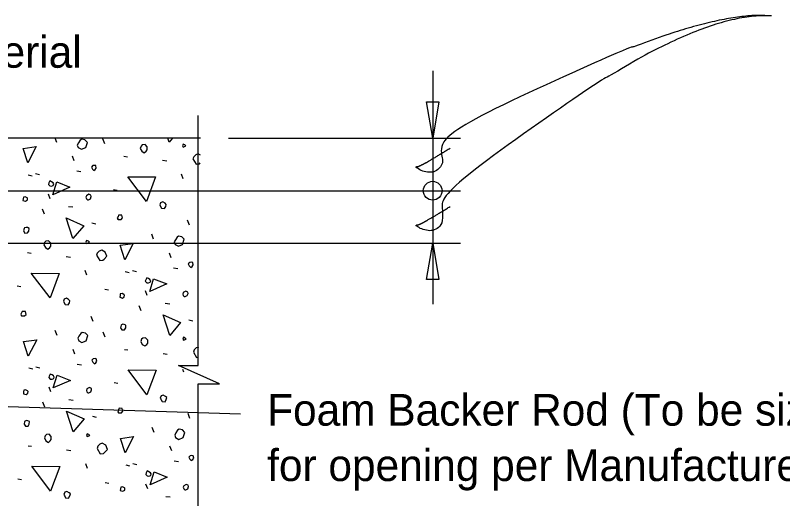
# Model space of a CAD drawing. Extents: x 0 to 15.4, y 0 to 9.7.
# Drawn here: x 5 to 6.829, y 3.173 to 4.325 of the extents above; entities that cross this region are included whole.
import ezdxf

# ---------------------------------------------------------------- set-up
doc = ezdxf.new("R2010")
doc.units = 0
for name, color, linetype in [('Dimension', 7, 'Continuous'), ('Miscellaneous', 7, 'Continuous'), ('SupstrConc', 7, 'Continuous'), ('TextStructures', 7, 'Continuous')]:
    doc.layers.add(name, color=color, linetype=linetype)

msp = doc.modelspace()

# ---------------------------------------------------------------- linework, layer by layer
at = {"layer": 'Dimension'}
for p, q in [((5.9943, 4.1934), (5.9943, 3.7182)), ((5.9943, 4.1934), (5.9943, 3.6362)), ((5.5074, 4.0322), (6.0609, 4.0322)), ((4.0652, 3.9072), (6.0609, 3.9072)), ((3.8815, 3.7822), (6.0609, 3.7822)), ((5.5362, 3.3743), (3.9985, 3.4235))]:
    msp.add_line(p, q, dxfattribs=at)
for points in [[(5.9943, 4.0322), (5.9796, 4.1188), (6.009, 4.1188)], [(5.9943, 3.7822), (6.009, 3.6956), (5.9796, 3.6956)]]:
    msp.add_lwpolyline(points, close=True, dxfattribs=at)
msp.add_lwpolyline([(5.4356, 3.1456), (5.4356, 3.4469), (5.4858, 3.4469), (5.3885, 3.49), (5.4356, 3.49), (5.4356, 4.0864)], dxfattribs=at)
msp.add_circle((5.9943, 3.9072), 0.0224, dxfattribs=at)
for points in [[(6.8022, 4.3242), (6.6382, 4.3342), (6.0095, 3.9095), (6.0223, 3.8373), (6.0027, 3.8119), (5.9747, 3.8119), (5.9501, 3.8255), (5.9654, 3.8255), (6.0358, 3.8696)], [(6.8022, 4.3242), (6.6621, 4.3379), (6.0095, 4.0487), (6.0223, 3.9766), (6.0027, 3.9511), (5.9747, 3.9511), (5.9501, 3.9647), (5.9654, 3.9647), (6.0358, 4.0088)]]:
    msp.add_open_spline(points, degree=2, dxfattribs=at)
at = {"layer": 'Miscellaneous'}
for p, q in [((5.0982, 4.0224), (5.0943, 4.0322)), ((5.2125, 4.0188), (5.2078, 4.0306)), ((5.5074, 4.0322), (6.0609, 4.0322)), ((5.14, 3.9782), (5.1359, 3.9894)), ((5.2585, 3.9894), (5.2667, 3.9882)), ((5.3504, 3.9799), (5.3604, 3.9782)), ((5.1459, 3.9546), (5.156, 3.9528)), ((5.0304, 3.9452), (5.0399, 3.9428)), ((5.0475, 3.9481), (5.057, 3.9458)), ((5.3999, 3.9352), (5.3958, 3.9464)), ((5.0829, 3.888), (5.0788, 3.8992)), ((5.2337, 3.9104), (5.2426, 3.9086)), ((5.0688, 3.8515), (5.064, 3.8633)), ((5.1259, 3.8698), (5.1365, 3.8686)), ((5.1819, 3.8303), (5.1913, 3.8279)), ((5.4146, 3.825), (5.4099, 3.8368)), ((5.3292, 3.7914), (5.3245, 3.8032)), ((5.0287, 3.7596), (5.0369, 3.7584)), ((5.1206, 3.7501), (5.1306, 3.7484)), ((5.371, 3.7472), (5.3669, 3.7584)), ((5.1701, 3.7054), (5.166, 3.7166)), ((5.2614, 3.7142), (5.2709, 3.7118)), ((5.2785, 3.7171), (5.288, 3.7148)), ((5.3769, 3.7236), (5.3869, 3.7219)), ((5.0039, 3.6806), (5.0128, 3.6788)), ((5.2125, 3.6724), (5.2214, 3.6706)), ((5.3139, 3.657), (5.3098, 3.6682)), ((5.2997, 3.6205), (5.295, 3.6323)), ((5.3569, 3.6388), (5.3675, 3.6376)), ((5.1848, 3.5952), (5.1801, 3.6069)), ((5.4129, 3.5993), (5.4223, 3.5969)), ((5.0994, 3.5616), (5.0947, 3.5734)), ((5.2137, 3.558), (5.209, 3.5698)), ((5.1412, 3.5174), (5.1371, 3.5286)), ((5.2597, 3.5286), (5.2679, 3.5274)), ((5.3516, 3.5192), (5.3616, 3.5174)), ((5.1471, 3.4938), (5.1571, 3.492)), ((5.0316, 3.4844), (5.0411, 3.482)), ((5.0487, 3.4873), (5.0581, 3.485)), ((5.4011, 3.4744), (5.3988, 3.4807)), ((5.2349, 3.4496), (5.2438, 3.4479)), ((5.0841, 3.4272), (5.0799, 3.4384)), ((5.0699, 3.3907), (5.0652, 3.4025)), ((5.1271, 3.409), (5.1377, 3.4078)), ((5.1831, 3.3695), (5.1925, 3.3671)), ((5.4158, 3.3642), (5.4111, 3.376)), ((5.3304, 3.3306), (5.3257, 3.3424)), ((5.0299, 3.2988), (5.0381, 3.2976)), ((5.3722, 3.2864), (5.3681, 3.2976)), ((5.1218, 3.2893), (5.1318, 3.2876)), ((5.1713, 3.2446), (5.1672, 3.2558)), ((5.2797, 3.2563), (5.2891, 3.254)), ((5.3781, 3.2628), (5.3881, 3.2611)), ((5.2626, 3.2534), (5.272, 3.251)), ((5.0051, 3.2198), (5.0139, 3.218)), ((5.2137, 3.2116), (5.2225, 3.2098)), ((5.3151, 3.1962), (5.3109, 3.2074)), ((5.3581, 3.178), (5.3687, 3.1768))]:
    msp.add_line(p, q, dxfattribs=at)
for points in [[(5.1495, 4.01), (5.1571, 4.0059), (5.1672, 4.01), (5.1713, 4.0224), (5.1654, 4.0283), (5.1577, 4.03), (5.1542, 4.0277), (5.1501, 4.0212), (5.1471, 4.0159), (5.1495, 4.01)], [(5.3663, 4.023), (5.3633, 4.0322)], [(5.3742, 4.0322), (5.3663, 4.023)], [(5.0293, 3.9735), (5.0181, 4.0082), (5.0493, 4.0124), (5.0293, 3.9735)], [(5.2974, 4.0082), (5.3009, 4.0012), (5.3068, 3.9976), (5.3115, 4.0012), (5.3139, 4.0047), (5.3139, 4.0118), (5.3086, 4.0171), (5.3021, 4.0165), (5.2991, 4.0135), (5.2974, 4.0082)], [(5.3993, 4.0112), (5.4058, 4.0141), (5.4034, 4.0165), (5.3993, 4.0183), (5.3976, 4.0141), (5.3993, 4.0112)], [(5.4405, 3.9923), (5.4353, 3.9953), (5.4294, 3.9929), (5.4247, 3.9882), (5.4229, 3.9829)], [(5.4229, 3.9829), (5.4306, 3.9705), (5.4382, 3.9711), (5.4404, 3.9733)], [(5.1831, 3.9587), (5.1866, 3.9552), (5.1901, 3.9576), (5.1925, 3.9611), (5.1913, 3.967), (5.1884, 3.9676), (5.1842, 3.967), (5.1807, 3.9634), (5.1831, 3.9587)], [(5.3121, 3.8815), (5.2673, 3.9405), (5.3339, 3.9399), (5.3121, 3.8815)], [(5.0817, 3.9187), (5.0858, 3.9181), (5.09, 3.9198), (5.0911, 3.9234), (5.0894, 3.9263), (5.0858, 3.9287), (5.0817, 3.9305), (5.0794, 3.9257), (5.0782, 3.9222), (5.0817, 3.9187)], [(5.0888, 3.8975), (5.0982, 3.9281), (5.1294, 3.9157), (5.0888, 3.8975)], [(5.1713, 3.8857), (5.1736, 3.8857), (5.1784, 3.888), (5.1801, 3.8933), (5.1795, 3.8963), (5.1748, 3.8986), (5.1689, 3.8951), (5.1677, 3.8916), (5.1689, 3.888), (5.1713, 3.8857)], [(5.0175, 3.8839), (5.024, 3.8821), (5.0281, 3.8851), (5.0287, 3.8892), (5.0275, 3.8904), (5.0228, 3.8927), (5.0187, 3.8921), (5.0181, 3.888), (5.0175, 3.8839)], [(5.3451, 3.8709), (5.3481, 3.8656), (5.3551, 3.8645), (5.3581, 3.8698), (5.3593, 3.8745), (5.3563, 3.8774), (5.351, 3.8804), (5.3457, 3.8786), (5.3439, 3.8733), (5.3451, 3.8709)], [(5.1365, 3.7932), (5.1206, 3.8421), (5.1624, 3.8238), (5.1365, 3.7932)], [(5.2443, 3.8385), (5.2514, 3.8385), (5.255, 3.8421), (5.2532, 3.8485), (5.2455, 3.8491), (5.2443, 3.8456), (5.2426, 3.8427), (5.2443, 3.8385), (5.2432, 3.8397)], [(5.0193, 3.8114), (5.0222, 3.8061), (5.0287, 3.8067), (5.0316, 3.8108), (5.0322, 3.8173), (5.0281, 3.8191), (5.0251, 3.8197), (5.0216, 3.8185), (5.0204, 3.8173), (5.0193, 3.8114)], [(5.0676, 3.7784), (5.0711, 3.7714), (5.077, 3.7678), (5.0817, 3.7714), (5.0841, 3.7749), (5.0841, 3.782), (5.0788, 3.7873), (5.0723, 3.7867), (5.0693, 3.7837), (5.0676, 3.7784)], [(5.1695, 3.7814), (5.176, 3.7843), (5.1736, 3.7867), (5.1695, 3.7884), (5.1677, 3.7843), (5.1695, 3.7814)], [(5.3805, 3.779), (5.3881, 3.7749), (5.3981, 3.779), (5.4023, 3.7914), (5.3964, 3.7973), (5.3887, 3.799), (5.3852, 3.7967), (5.3811, 3.7902), (5.3781, 3.7849), (5.3805, 3.779)], [(5.2603, 3.7425), (5.2491, 3.7772), (5.2803, 3.7814), (5.2603, 3.7425)], [(5.1931, 3.7531), (5.2007, 3.7407), (5.2084, 3.7413), (5.2113, 3.7442), (5.2178, 3.7507), (5.2137, 3.7607), (5.2055, 3.7655), (5.1996, 3.7631), (5.1949, 3.7584), (5.1931, 3.7531)], [(5.4141, 3.7277), (5.4176, 3.7242), (5.4211, 3.7266), (5.4235, 3.7301), (5.4223, 3.736), (5.4194, 3.7366), (5.4152, 3.736), (5.4117, 3.7325), (5.4141, 3.7277)], [(5.0823, 3.6517), (5.0375, 3.7107), (5.1041, 3.7101), (5.0823, 3.6517)], [(5.3127, 3.6877), (5.3168, 3.6871), (5.321, 3.6889), (5.3221, 3.6924), (5.3204, 3.6953), (5.3168, 3.6977), (5.3127, 3.6995), (5.3103, 3.6947), (5.3092, 3.6912), (5.3127, 3.6877)], [(5.3198, 3.6665), (5.3292, 3.6971), (5.3604, 3.6847), (5.3198, 3.6665)], [(5.2485, 3.6529), (5.255, 3.6511), (5.2591, 3.6541), (5.2597, 3.6582), (5.2585, 3.6594), (5.2538, 3.6618), (5.2497, 3.6612), (5.2491, 3.657), (5.2485, 3.6529)], [(5.4023, 3.6547), (5.4046, 3.6547), (5.4093, 3.657), (5.4111, 3.6623), (5.4105, 3.6653), (5.4058, 3.6676), (5.3999, 3.6641), (5.3987, 3.6606), (5.3999, 3.657), (5.4023, 3.6547)], [(5.1153, 3.6411), (5.1182, 3.6358), (5.1253, 3.6346), (5.1283, 3.6399), (5.1294, 3.6447), (5.1265, 3.6476), (5.1212, 3.6506), (5.1159, 3.6488), (5.1141, 3.6435), (5.1153, 3.6411)], [(5.0145, 3.6087), (5.0216, 3.6087), (5.0251, 3.6123), (5.0234, 3.6187), (5.0157, 3.6193), (5.0145, 3.6158), (5.0128, 3.6128), (5.0145, 3.6087), (5.0134, 3.6099)], [(5.3675, 3.5622), (5.3516, 3.6111), (5.3934, 3.5928), (5.3675, 3.5622)], [(5.2502, 3.5804), (5.2532, 3.5751), (5.2597, 3.5757), (5.2626, 3.5798), (5.2632, 3.5863), (5.2591, 3.5881), (5.2561, 3.5887), (5.2526, 3.5875), (5.2514, 3.5863), (5.2502, 3.5804)], [(5.1507, 3.5492), (5.1583, 3.5451), (5.1683, 3.5492), (5.1725, 3.5616), (5.1666, 3.5675), (5.1589, 3.5692), (5.1554, 3.5669), (5.1512, 3.5604), (5.1483, 3.5551), (5.1507, 3.5492)], [(5.0304, 3.5127), (5.0193, 3.5474), (5.0505, 3.5516), (5.0304, 3.5127)], [(5.2986, 3.5474), (5.3021, 3.5404), (5.308, 3.5368), (5.3127, 3.5404), (5.3151, 3.5439), (5.3151, 3.551), (5.3098, 3.5563), (5.3033, 3.5557), (5.3003, 3.5527), (5.2986, 3.5474)], [(5.4005, 3.5504), (5.407, 3.5533), (5.4046, 3.5557), (5.4005, 3.5575), (5.3987, 3.5533), (5.4005, 3.5504)], [(5.4361, 3.5343), (5.4306, 3.5321), (5.4258, 3.5274), (5.4241, 3.5221)], [(5.4241, 3.5221), (5.4317, 3.5097), (5.4358, 3.51)], [(5.1842, 3.4979), (5.1878, 3.4944), (5.1913, 3.4968), (5.1937, 3.5003), (5.1925, 3.5062), (5.1895, 3.5068), (5.1854, 3.5062), (5.1819, 3.5027), (5.1842, 3.4979)], [(5.3133, 3.4207), (5.2685, 3.4797), (5.3351, 3.4791), (5.3133, 3.4207)], [(5.0829, 3.4579), (5.087, 3.4573), (5.0911, 3.459), (5.0923, 3.4626), (5.0906, 3.4655), (5.087, 3.4679), (5.0829, 3.4697), (5.0805, 3.4649), (5.0794, 3.4614), (5.0829, 3.4579)], [(5.09, 3.4367), (5.0994, 3.4673), (5.1306, 3.4549), (5.09, 3.4367)], [(5.0187, 3.4231), (5.0251, 3.4213), (5.0293, 3.4243), (5.0299, 3.4284), (5.0287, 3.4296), (5.024, 3.4319), (5.0198, 3.4314), (5.0193, 3.4272), (5.0187, 3.4231)], [(5.1725, 3.4249), (5.1748, 3.4249), (5.1795, 3.4272), (5.1813, 3.4325), (5.1807, 3.4355), (5.176, 3.4378), (5.1701, 3.4343), (5.1689, 3.4308), (5.1701, 3.4272), (5.1725, 3.4249)], [(5.3463, 3.4101), (5.3492, 3.4048), (5.3563, 3.4037), (5.3593, 3.409), (5.3604, 3.4137), (5.3575, 3.4166), (5.3522, 3.4196), (5.3469, 3.4178), (5.3451, 3.4125), (5.3463, 3.4101)], [(5.2455, 3.3777), (5.2526, 3.3777), (5.2561, 3.3813), (5.2544, 3.3877), (5.2467, 3.3883), (5.2455, 3.3848), (5.2438, 3.3819), (5.2455, 3.3777), (5.2443, 3.3789)], [(5.1377, 3.3324), (5.1218, 3.3813), (5.1636, 3.363), (5.1377, 3.3324)], [(5.0204, 3.3506), (5.0234, 3.3453), (5.0299, 3.3459), (5.0328, 3.35), (5.0334, 3.3565), (5.0293, 3.3583), (5.0263, 3.3589), (5.0228, 3.3577), (5.0216, 3.3565), (5.0204, 3.3506)], [(5.3816, 3.3182), (5.3893, 3.3141), (5.3993, 3.3182), (5.4034, 3.3306), (5.3976, 3.3365), (5.3899, 3.3382), (5.3864, 3.3359), (5.3822, 3.3294), (5.3793, 3.3241), (5.3816, 3.3182)], [(5.0688, 3.3176), (5.0723, 3.3106), (5.0782, 3.307), (5.0829, 3.3106), (5.0852, 3.3141), (5.0852, 3.3212), (5.0799, 3.3265), (5.0735, 3.3259), (5.0705, 3.3229), (5.0688, 3.3176)], [(5.1707, 3.3206), (5.1772, 3.3235), (5.1748, 3.3259), (5.1707, 3.3276), (5.1689, 3.3235), (5.1707, 3.3206)], [(5.2614, 3.2817), (5.2502, 3.3164), (5.2815, 3.3206), (5.2614, 3.2817)], [(5.1943, 3.2923), (5.2019, 3.2799), (5.2096, 3.2805), (5.2125, 3.2834), (5.219, 3.2899), (5.2149, 3.2999), (5.2066, 3.3047), (5.2007, 3.3023), (5.196, 3.2976), (5.1943, 3.2923)], [(5.4152, 3.2669), (5.4188, 3.2634), (5.4223, 3.2658), (5.4247, 3.2693), (5.4235, 3.2752), (5.4205, 3.2758), (5.4164, 3.2752), (5.4129, 3.2717), (5.4152, 3.2669)], [(5.0835, 3.1909), (5.0387, 3.2499), (5.1053, 3.2493), (5.0835, 3.1909)], [(5.3139, 3.2269), (5.318, 3.2263), (5.3221, 3.2281), (5.3233, 3.2316), (5.3215, 3.2345), (5.318, 3.2369), (5.3139, 3.2387), (5.3115, 3.234), (5.3103, 3.2304), (5.3139, 3.2269)], [(5.321, 3.2057), (5.3304, 3.2363), (5.3616, 3.2239), (5.321, 3.2057)], [(5.2497, 3.1921), (5.2561, 3.1903), (5.2603, 3.1933), (5.2608, 3.1974), (5.2597, 3.1986), (5.255, 3.201), (5.2508, 3.2004), (5.2502, 3.1962), (5.2497, 3.1921)], [(5.4034, 3.1939), (5.4058, 3.1939), (5.4105, 3.1962), (5.4123, 3.2015), (5.4117, 3.2045), (5.407, 3.2068), (5.4011, 3.2033), (5.3999, 3.1998), (5.4011, 3.1962), (5.4034, 3.1939)], [(5.1165, 3.1803), (5.1194, 3.175), (5.1265, 3.1738), (5.1294, 3.1792), (5.1306, 3.1839), (5.1277, 3.1868), (5.1224, 3.1898), (5.1171, 3.188), (5.1153, 3.1827), (5.1165, 3.1803)]]:
    msp.add_lwpolyline(points, dxfattribs=at)
at = {"layer": 'SupstrConc'}
msp.add_line((5.4409, 4.0322), (4.061, 4.0322), dxfattribs=at)

# ---------------------------------------------------------------- texts
at = {"layer": 'Dimension'}
for s, p in [('Foam Backer Rod (To be sized ', (5.5997, 3.3467)), ("for opening per Manufacturer's ", (5.5997, 3.2147))]:
    msp.add_text(s, height=0.0756, dxfattribs=at).set_placement(p)
at = {"layer": 'TextStructures'}
msp.add_text('Poured Joint Material', height=0.0756, dxfattribs=at).set_placement((4.2024, 4.2005))

doc.saveas('drawing.dxf')
